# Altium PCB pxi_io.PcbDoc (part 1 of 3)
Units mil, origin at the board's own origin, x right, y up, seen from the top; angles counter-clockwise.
Board outline 6300 x 3935 mil, 2 copper layers (Top Layer, Bottom Layer); 257 components, 420 nets, 1532 pads, 239 vias.
Unrouted connection lines stored in the file: 158.
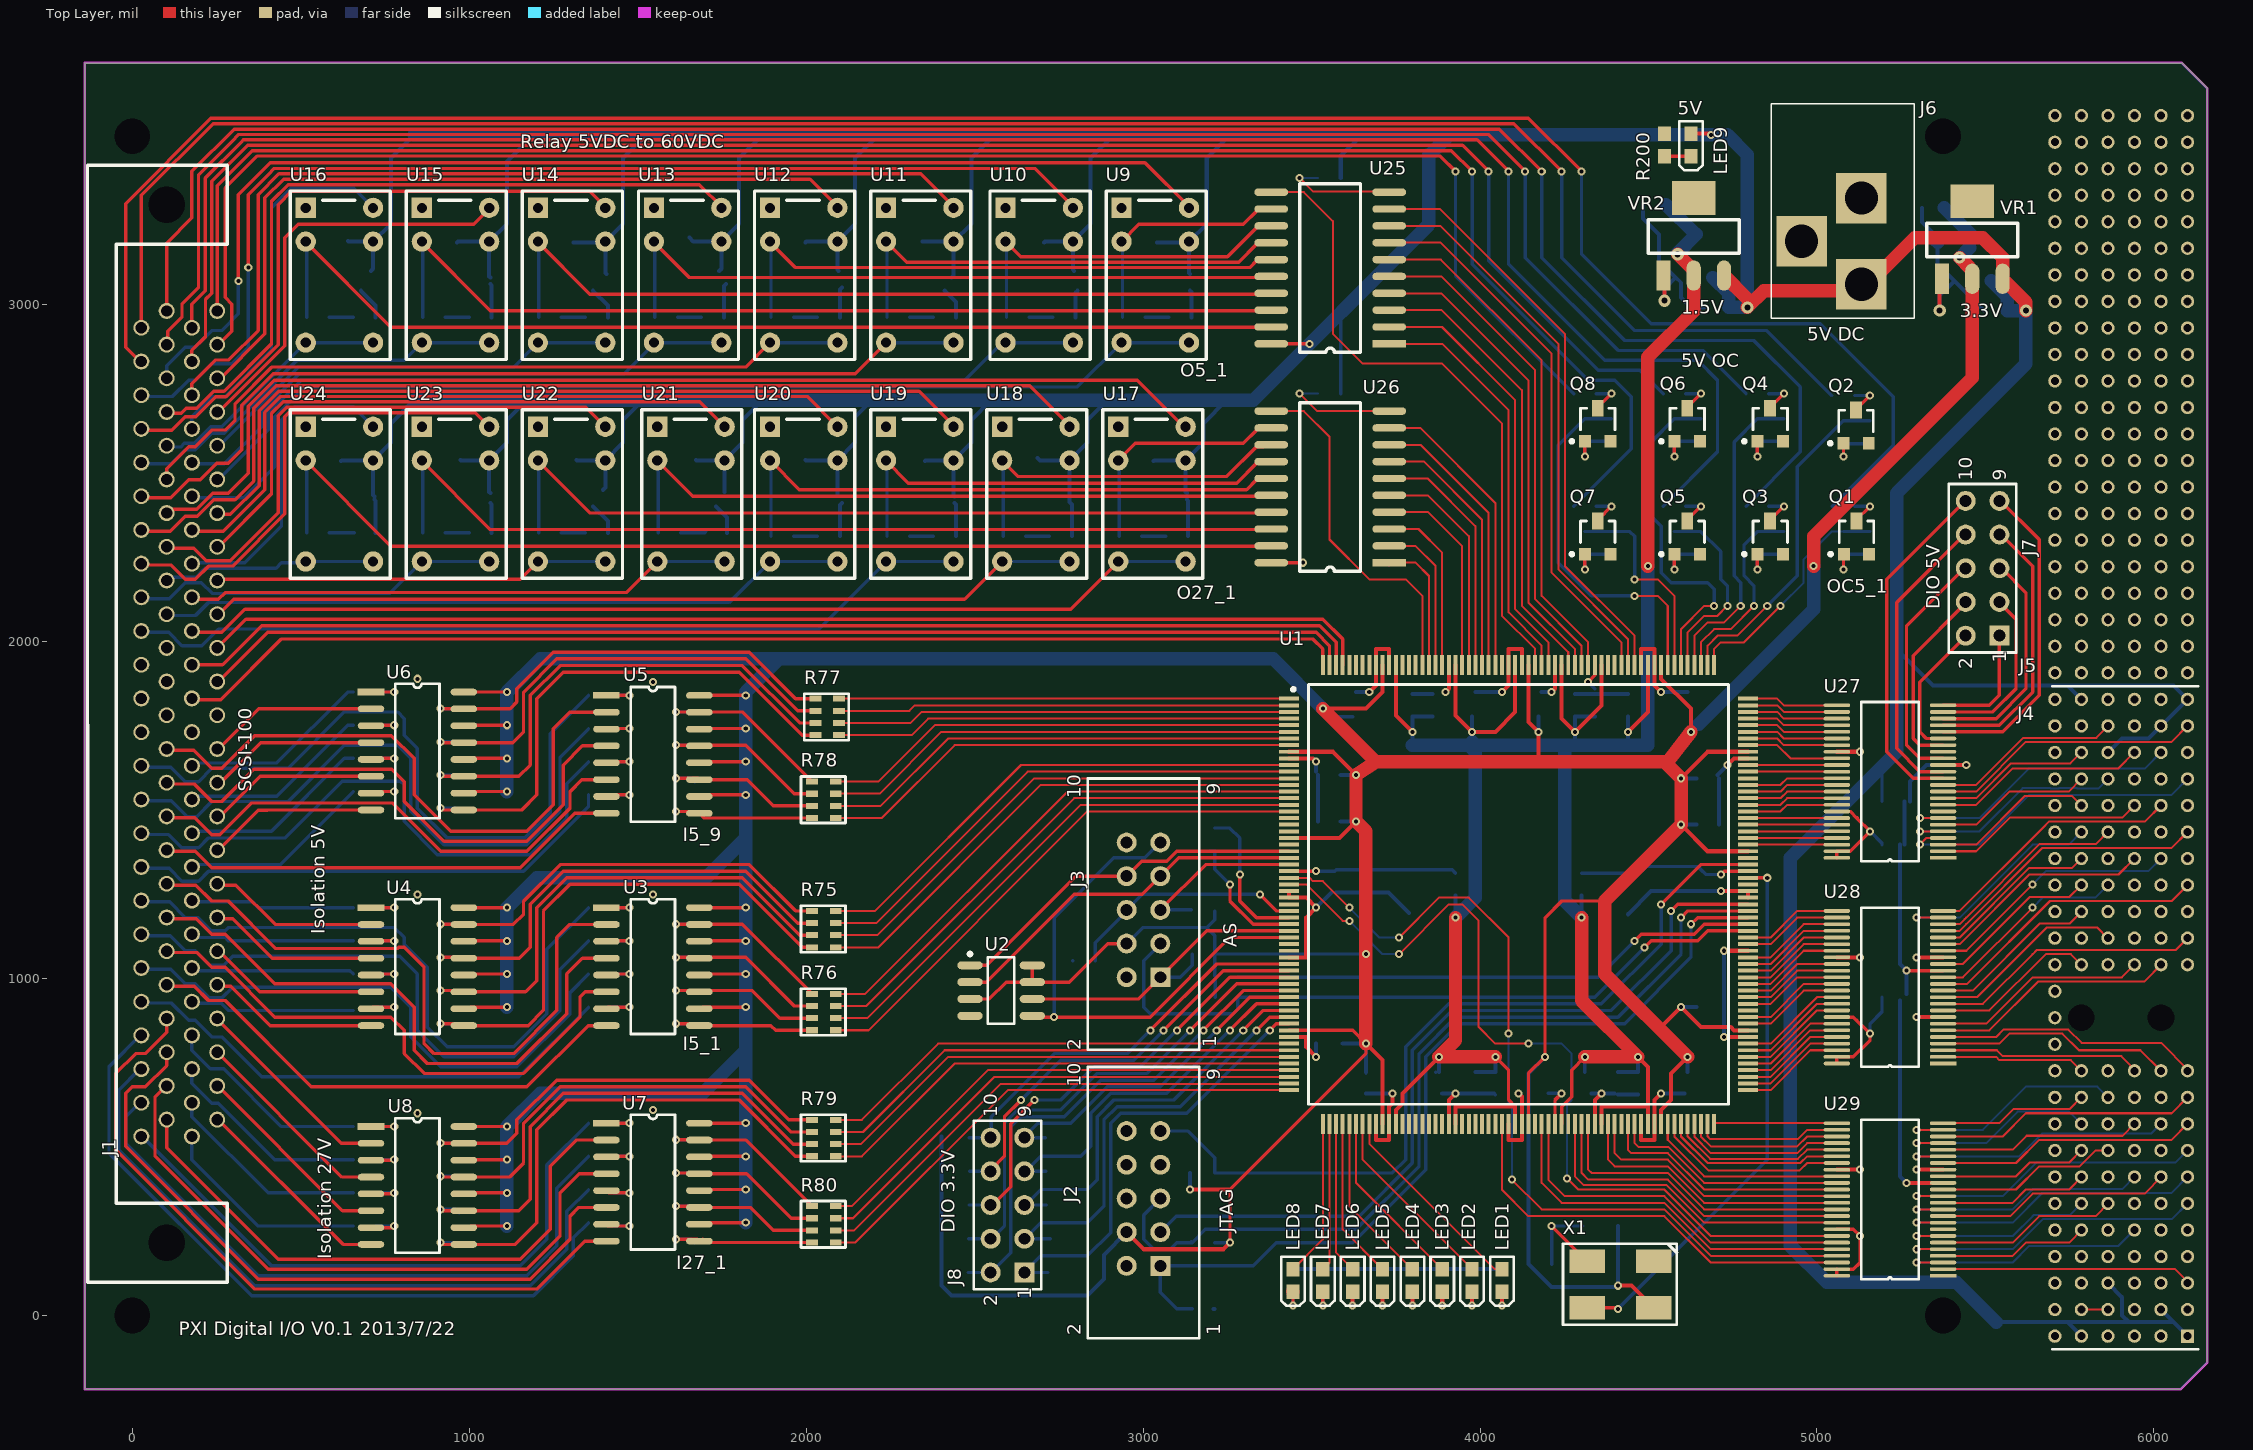
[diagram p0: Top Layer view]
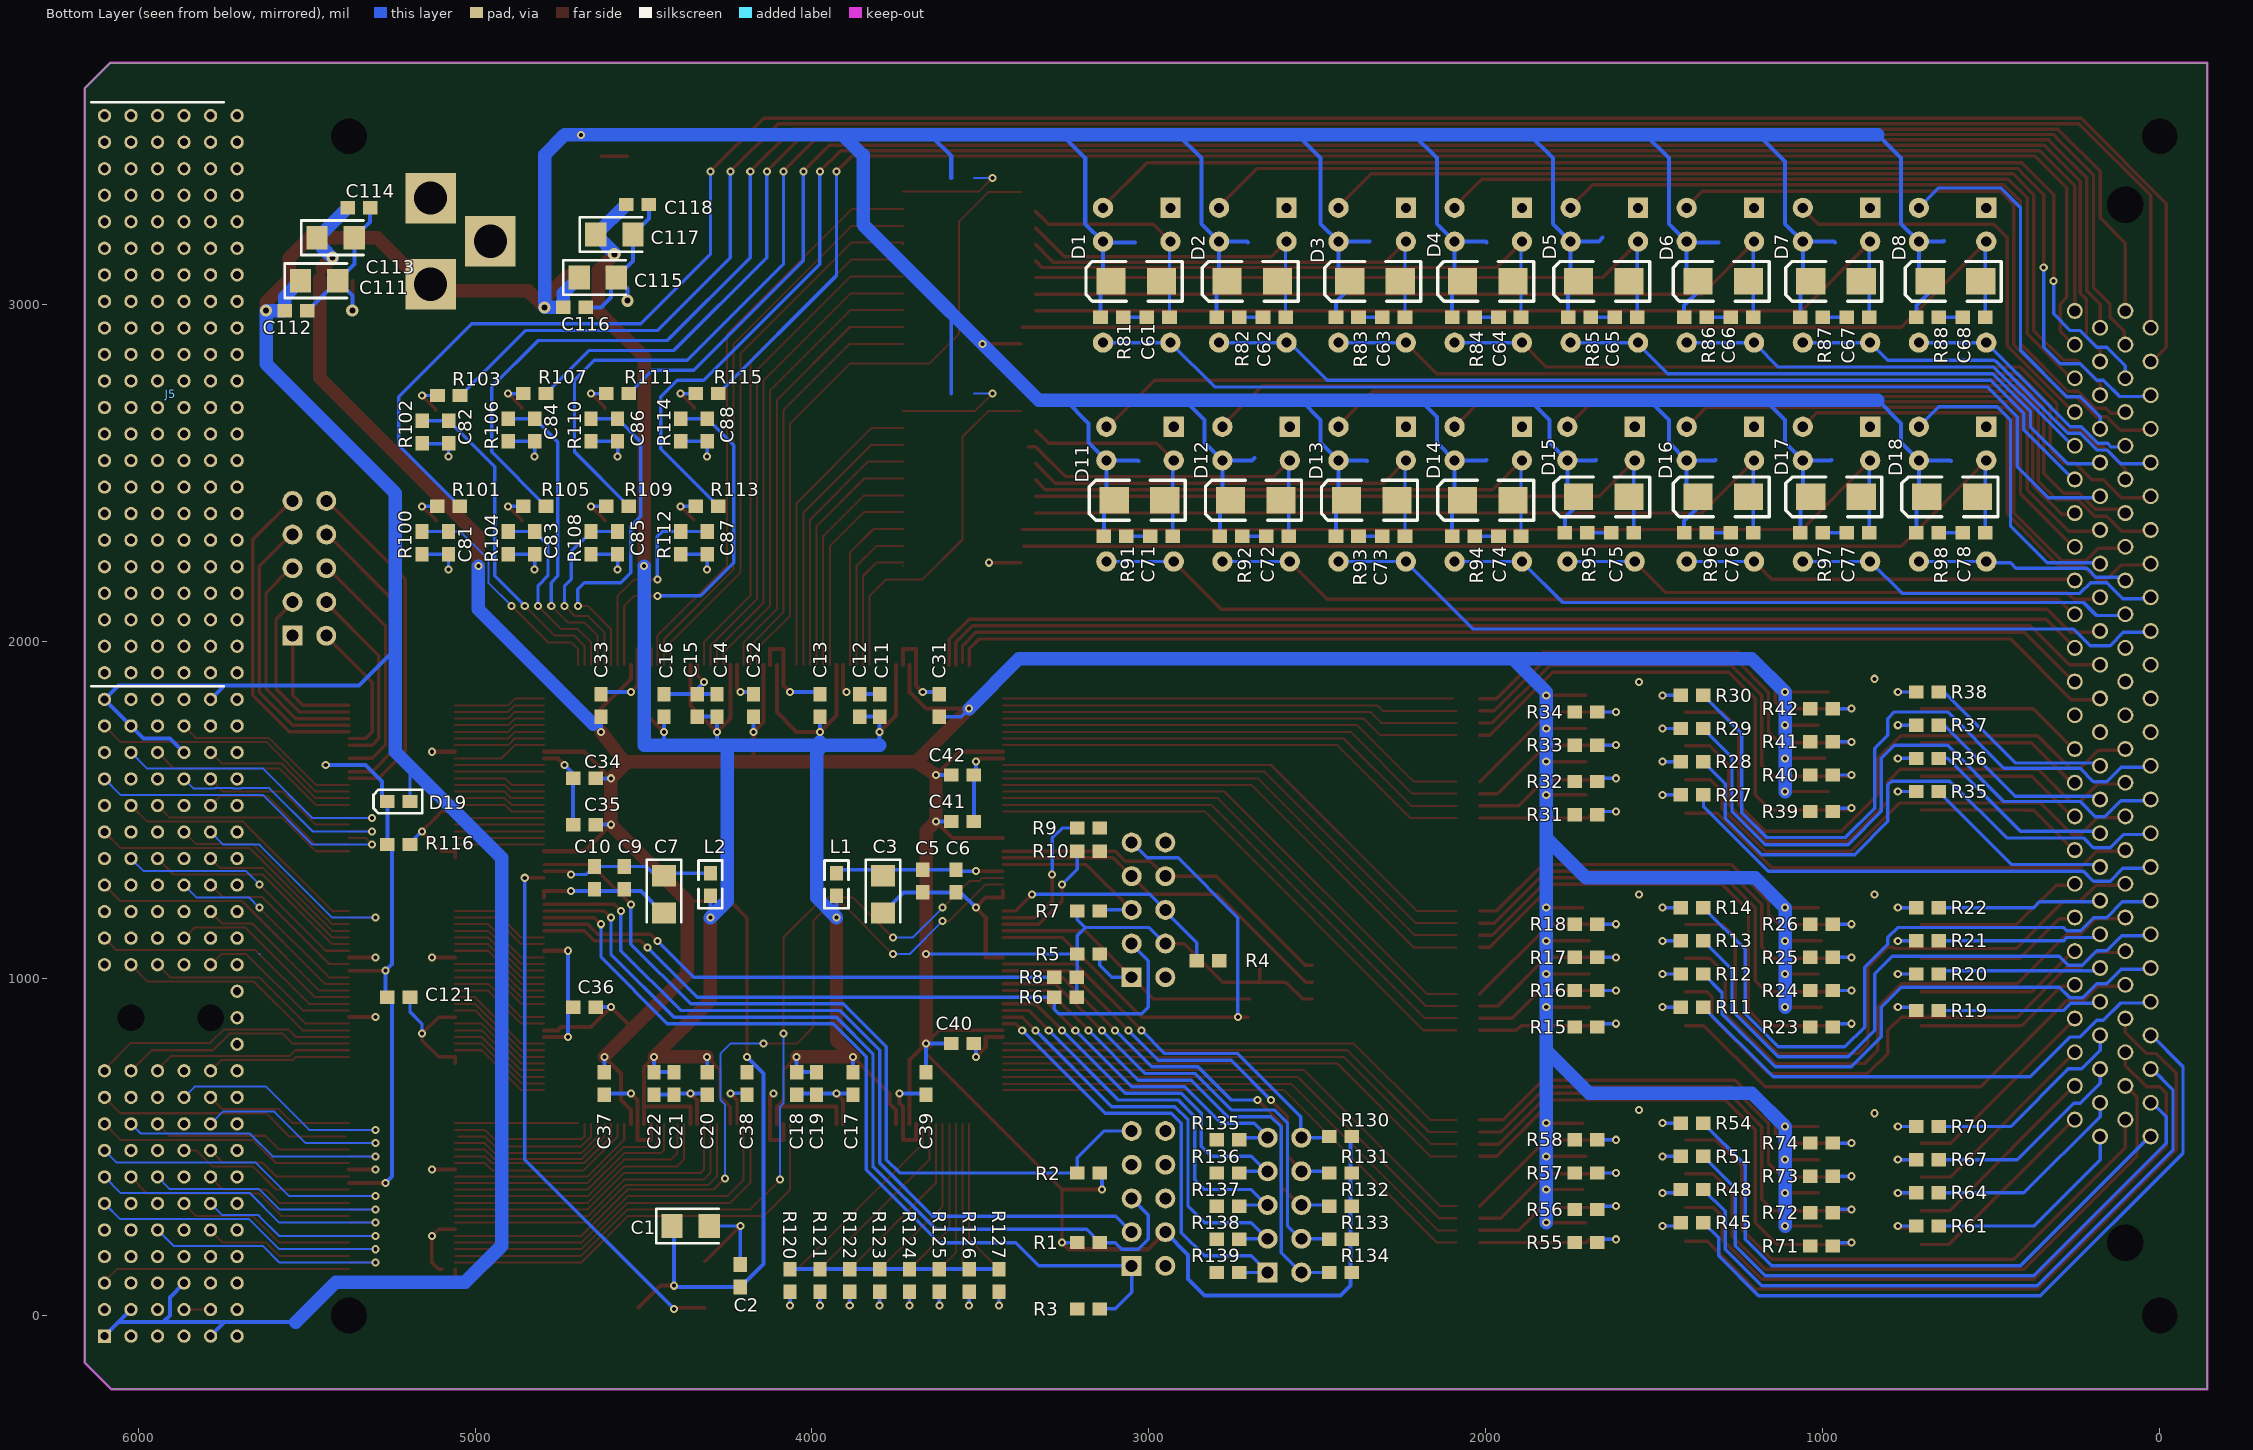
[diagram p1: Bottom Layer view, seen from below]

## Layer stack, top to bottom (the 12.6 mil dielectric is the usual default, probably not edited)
Top Layer: signal copper 1.4
Dielectric: core 12.6, FR-4, Dk 4.8
Bottom Layer: signal copper 1.4

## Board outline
-141.34,3717.05 6083.66,3717.05 6158.66,3642.05 6158.66,3637.05 6158.66,-137.95 6078.66,-217.95 -141.34,-217.95

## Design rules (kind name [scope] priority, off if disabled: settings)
Clearance [All] p1: gap=6
ComponentClearance [All] p1: gap=0 collisioncheckmode=3 verticalgap=10 showdistances=FALSE
FabricationTestPointUsage TestPointUsage [All] p1: valid=0 allowmultiple=FALSE
FabricationTestpoint Testpoint [All] p1: side=3 testpointundercomponent=TRUE minsize=40 maxsize=100 preferedsize=60 minholesize=0 maxholesize=40 preferedholesize=32 testpointgrid=1 allowsidetop=TRUE allowsidebottom=TRUE usegrid=TRUE gridtolerance=0.01
PolygonConnect [All] p1: connectstyle=Relief reliefconductorwidth=10 reliefentries=4 polygonreliefangle="90 Angle"
RoutingVias [All] p1: holewidth=28 width=50 viastyle="Through Hole" minholewidth=12 minwidth=24 maxholewidth=28 maxwidth=50
SilkscreenOverComponentPads [All] p1: minsilkscreentomaskgap=10
SolderMaskExpansion [All] p1: expansion=4
Width [All] p1: maxlimit=40 minlimit=6 preferedwidth=6
24 further rules are at their usual default settings.

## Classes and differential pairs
component class pxi_io: J1
component class pxi: C111 C112 C113 C114 C115 C116 C117 C118 C121 D19 J4 J5 J6 J7 LED9 R116 R200 U27 U28 U29 VR1 VR2
component class fpga: C1 C2 C3 C5 C6 C7 C9 C10 C11 C12 C13 C14 C15 C16 C17 C18 C19 C20 C21 C22 C31 C32 C33 C34 C35 C36 C37 C38 C39 C40 C41 C42 J2 J3 J8 L1 L2 LED1 LED2 LED3 LED4 LED5 LED6 LED7 LED8 R1 R2 R3 R4 R5 R6 R7 R8 R9 R10 R120 R121 R122 R123 R124 R125 R126 R127 R130 R131 R132 R133 R134 R135 R136 R137 R138 R139 U1 U2 X1
component class digit_out: C61 C62 C63 C64 C65 C66 C67 C68 C71 C72 C73 C74 C75 C76 C77 C78 C81 C82 C83 C84 C85 C86 C87 C88 D1 D2 D3 D4 D5 D6 D7 D8 D11 D12 D13 D14 D15 D16 D17 D18 Q1 Q2 Q3 Q4 Q5 Q6 Q7 Q8 R81 R82 R83 R84 R85 R86 R87 R88 R91 R92 R93 R94 R95 R96 R97 R98 R100 R101 R102 R103 R104 R105 R106 R107 R108 R109 R110 R111 R112 R113 R114 R115 U9 U10 U11 U12 U13 U14 U15 U16 U17 U18 U19 U20 U21 U22 U23 U24 U25 U26
component class digit_in: R11 R12 R13 R14 R15 R16 R17 R18 R19 R20 R21 R22 R23 R24 R25 R26 R27 R28 R29 R30 R31 R32 R33 R34 R35 R36 R37 R38 R39 R40 R41 R42 R45 R48 R51 R54 R55 R56 R57 R58 R61 R64 R67 R70 R71 R72 R73 R74 R75 R76 R77 R78 R79 R80 U3 U4 U5 U6 U7 U8

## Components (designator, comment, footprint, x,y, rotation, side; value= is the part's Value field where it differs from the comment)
C1 "Cap Pol3" CC3216-1206 4360.24,265.75 r180 bottom
C2 "Cap Semi" 1608[0603] 4212.6,118.11 r270 bottom
C3 "Cap Pol3" CC3216-1206 3789.37,1250 r270 bottom
C5 "Cap Semi" 1608[0603] 3671.26,1289.37 r90 bottom
C6 "Cap Semi" 1608[0603] 3572.83,1289.37 r90 bottom
C7 "Cap Pol3" CC3216-1206 4438.98,1250 r270 bottom
C9 "Cap Semi" 1608[0603] 4557.09,1299.21 r90 bottom
C10 "Cap Semi" 1608[0603] 4645.67,1299.21 r90 bottom
C11 "Cap Semi" 1608[0603] 3799.21,1811.02 r270 bottom
C12 "Cap Semi" 1608[0603] 3858.27,1811.02 r270 bottom
C13 "Cap Semi" 1608[0603] 3976.38,1811.02 r270 bottom
C14 "Cap Semi" 1608[0603] 4281.5,1811.02 r270 bottom
C15 "Cap Semi" 1608[0603] 4340.55,1811.02 r270 bottom
C16 "Cap Semi" 1608[0603] 4438.98,1811.02 r270 bottom
C17 "Cap Semi" 1608[0603] 3877.95,688.98 r90 bottom
C18 "Cap Semi" 1608[0603] 4045.28,688.98 r90 bottom
C19 "Cap Semi" 1608[0603] 3986.22,688.98 r90 bottom
C20 "Cap Semi" 1608[0603] 4311.02,688.98 r90 bottom
C21 "Cap Semi" 1608[0603] 4409.45,688.98 r90 bottom
C22 "Cap Semi" 1608[0603] 4468.5,688.98 r90 bottom
C31 "Cap Semi" 1608[0603] 3622.05,1811.02 r270 bottom
C32 "Cap Semi" 1608[0603] 4173.23,1811.02 r270 bottom
C33 "Cap Semi" 1608[0603] 4625.98,1811.02 r270 bottom
C34 "Cap Semi" 1608[0603] 4675.2,1594.49 r180 bottom
C35 "Cap Semi" 1608[0603] 4675.2,1456.69 r180 bottom
C36 "Cap Semi" 1608[0603] 4675.2,915.35 r180 bottom
C37 "Cap Semi" 1608[0603] 4616.14,688.98 r90 bottom
C38 "Cap Semi" 1608[0603] 4192.91,688.98 r90 bottom
C39 "Cap Semi" 1608[0603] 3661.42,688.98 r90 bottom
C40 "Cap Semi" 1608[0603] 3553.15,807.09 r0 bottom
C41 "Cap Semi" 1608[0603] 3553.15,1466.54 r0 bottom
C42 "Cap Semi" 1608[0603] 3553.15,1604.33 r0 bottom
C61 "Cap Semi" 1608[0603] 2972.44,2962.6 r180 bottom
C62 "Cap Semi" 1608[0603] 2627.95,2962.6 r180 bottom
C63 "Cap Semi" 1608[0603] 2273.62,2962.6 r180 bottom
C64 "Cap Semi" 1608[0603] 1929.13,2962.6 r180 bottom
C65 "Cap Semi" 1608[0603] 1584.65,2962.6 r180 bottom
C66 "Cap Semi" 1608[0603] 1240.16,2962.6 r180 bottom
C67 "Cap Semi" 1608[0603] 895.67,2962.6 r180 bottom
C68 "Cap Semi" 1608[0603] 551.18,2962.6 r180 bottom
C71 "Cap Semi" 1608[0603] 2962.6,2312.99 r180 bottom
C72 "Cap Semi" 1608[0603] 2618.11,2312.99 r180 bottom
C73 "Cap Semi" 1608[0603] 2273.62,2312.99 r180 bottom
C74 "Cap Semi" 1608[0603] 1929.13,2312.99 r180 bottom
C75 "Cap Semi" 1608[0603] 1594.49,2322.83 r180 bottom
C76 "Cap Semi" 1608[0603] 1240.16,2322.83 r180 bottom
C77 "Cap Semi" 1608[0603] 895.67,2322.83 r180 bottom
C78 "Cap Semi" 1608[0603] 551.18,2322.83 r180 bottom
C81 "Cap Semi" 1608[0603] 5078.74,2293.31 r90 bottom
C82 "Cap Semi" 1608[0603] 5077.88,2622.1 r90 bottom
C83 "Cap Semi" 1608[0603] 4822.83,2293.31 r90 bottom
C84 "Cap Semi" 1608[0603] 4822.83,2627.95 r90 bottom
C85 "Cap Semi" 1608[0603] 4576.77,2293.31 r90 bottom
C86 "Cap Semi" 1608[0603] 4576.77,2627.95 r90 bottom
C87 "Cap Semi" 1608[0603] 4311.02,2293.31 r90 bottom
C88 "Cap Semi" 1608[0603] 4311.02,2627.95 r90 bottom
C111 "Cap Pol3" CC3216-1206 5462.6,3070.87 r180 bottom
C112 "Cap Semi" 1608[0603] 5531.5,2982.28 r0 bottom
C113 "Cap Pol3" CC3216-1206 5413.39,3198.82 r180 bottom
C114 "Cap Semi" 1608[0603] 5344.49,3287.4 r0 bottom
C115 "Cap Pol3" CC3216-1206 4635.83,3080.71 r180 bottom
C116 "Cap Semi" 1608[0603] 4704.72,2992.13 r0 bottom
C117 "Cap Pol3" CC3216-1206 4586.61,3208.66 r180 bottom
C118 "Cap Semi" 1608[0603] 4517.72,3297.24 r0 bottom
C121 "Cap Semi" 1608[0603] 5226.38,944.88 r0 bottom
D1 "Diode" IN5817 2962.6,3169.29 r0 bottom
D2 "Diode" IN5817 2618.11,3169.29 r0 bottom
D3 "Diode" IN5817 2253.94,3169.29 r0 bottom
D4 "Diode" IN5817 1919.29,3169.29 r0 bottom
D5 "Diode" IN5817 1574.8,3169.29 r0 bottom
D6 "Diode" IN5817 1220.47,3169.29 r0 bottom
D7 "Diode" IN5817 885.83,3169.29 r0 bottom
D8 "Diode" IN5817 531.5,3169.29 r0 bottom
D11 "Diode" IN5817 2952.76,2519.69 r0 bottom
D12 "Diode" IN5817 2608.27,2519.69 r0 bottom
D13 "Diode" IN5817 2263.78,2519.69 r0 bottom
D14 "Diode" IN5817 1919.29,2519.69 r0 bottom
D15 "Diode" IN5817 1574.8,2529.53 r0 bottom
D16 "Diode" IN5817 1220.47,2529.53 r0 bottom
D17 "Diode" IN5817 885.83,2529.53 r0 bottom
D18 "Diode" IN5817 541.34,2529.53 r0 bottom
D19 "Diode" D1608-0603 5226.38,1525.59 r0 bottom
J1 "Connector 100" SCSI-100 177.17,531.5 r90 top locked
J2 "Header 5X2" HDR2X5_JTAG 3051.18,147.64 r90 top locked
J3 "Header 5X2" HDR2X5_JTAG 3051.18,1003.94 r90 top locked
J4 "352068-1" BTB2-H135F 6099.61,-61.02 r90 top locked
J5 "352152-1" BTB2-H132FA 6099.61,1907.48 r270 bottom locked
J6 "PWP_CON" POWER_CON_EXTERN 5088.58,3346.46 r90 top locked
J7 "DIO 5V" HDR2X5 5541.34,2017.72 r90 top locked
J8 "DIO 3.3V" HDR2X5 2647.64,127.95 r90 top locked
L1 "Inductor" C1608-0603 3927.17,1279.53 r90 bottom
L2 "Inductor" C1608-0603 4301.18,1279.53 r90 bottom
LED1 "LED2" D1608-0603 4064.96,104.33 r270 top
LED2 "LED2" D1608-0603 3976.38,104.33 r270 top
LED3 "LED2" D1608-0603 3887.8,104.33 r270 top
LED4 "LED2" D1608-0603 3799.21,104.33 r270 top
LED5 "LED2" D1608-0603 3710.63,104.33 r270 top
LED6 "LED2" D1608-0603 3622.05,104.33 r270 top
LED7 "LED2" D1608-0603 3533.46,104.33 r270 top
LED8 "LED2" D1608-0603 3444.88,104.33 r270 top
LED9 "LED2" D1608-0603 4625.98,3474.41 r270 top
Q1 "QNPN" SO3 5000,2500 r0 top
Q2 "QNPN" SO3 4999.14,2828.8 r0 top
Q3 "QNPN" SO3 4744.09,2500 r0 top
Q4 "QNPN" SO3 4744.09,2834.65 r0 top
Q5 "QNPN" SO3 4498.03,2500 r0 top
Q6 "QNPN" SO3 4498.03,2834.65 r0 top
Q7 "QNPN" SO3 4232.28,2500 r0 top
Q8 "QNPN" SO3 4232.28,2834.65 r0 top
R1 "Res Semi" 1608[0603] 3179.13,216.54 r0 bottom
R2 "Res Semi" 1608[0603] 3179.13,423.23 r180 bottom
R3 "Res Semi" 1608[0603] 3179.13,19.68 r0 bottom
R4 "Res Semi" 1608[0603] 2824.8,1053.15 r0 bottom
R5 "Res Semi" 1608[0603] 3179.13,1072.83 r180 bottom
R6 "Res Semi" 1608[0603] 3248.03,944.88 r0 bottom
R7 "Res Semi" 1608[0603] 3179.13,1200.79 r180 bottom
R8 "Res Semi" 1608[0603] 3248.03,1003.94 r0 bottom
R9 "Res Semi" 1608[0603] 3179.13,1446.85 r180 bottom
R10 "Res Semi" 1608[0603] 3179.13,1377.95 r180 bottom
R11 "Res Semi" 1608[0603] 1387.8,915.35 r0 bottom
R12 "Res Semi" 1608[0603] 1387.8,1013.78 r0 bottom
R13 "Res Semi" 1608[0603] 1387.8,1112.2 r0 bottom
R14 "Res Semi" 1608[0603] 1387.8,1210.63 r0 bottom
R15 "Res Semi" 1608[0603] 1702.76,856.3 r0 bottom
R16 "Res Semi" 1608[0603] 1702.76,964.57 r0 bottom
R17 "Res Semi" 1608[0603] 1702.76,1062.99 r0 bottom
R18 "Res Semi" 1608[0603] 1702.76,1161.42 r0 bottom
R19 "Res Semi" 1608[0603] 688.98,905.51 r0 bottom
R20 "Res Semi" 1608[0603] 688.98,1013.78 r0 bottom
R21 "Res Semi" 1608[0603] 688.98,1112.2 r0 bottom
R22 "Res Semi" 1608[0603] 688.98,1210.63 r0 bottom
R23 "Res Semi" 1608[0603] 1003.94,856.3 r0 bottom
R24 "Res Semi" 1608[0603] 1003.94,964.57 r0 bottom
R25 "Res Semi" 1608[0603] 1003.94,1062.99 r0 bottom
R26 "Res Semi" 1608[0603] 1003.94,1161.42 r0 bottom
R27 "Res Semi" 1608[0603] 1387.8,1545.28 r0 bottom
R28 "Res Semi" 1608[0603] 1387.8,1643.7 r0 bottom
R29 "Res Semi" 1608[0603] 1387.8,1742.13 r0 bottom
R30 "Res Semi" 1608[0603] 1387.8,1840.55 r0 bottom
R31 "Res Semi" 1608[0603] 1702.76,1486.22 r0 bottom
R32 "Res Semi" 1608[0603] 1702.76,1584.65 r0 bottom
R33 "Res Semi" 1608[0603] 1702.76,1692.91 r0 bottom
R34 "Res Semi" 1608[0603] 1702.76,1791.34 r0 bottom
R35 "Res Semi" 1608[0603] 688.98,1555.12 r0 bottom
R36 "Res Semi" 1608[0603] 688.98,1653.54 r0 bottom
R37 "Res Semi" 1608[0603] 688.98,1751.97 r0 bottom
R38 "Res Semi" 1608[0603] 688.98,1850.39 r0 bottom
R39 "Res Semi" 1608[0603] 1003.94,1496.06 r0 bottom
R40 "Res Semi" 1608[0603] 1003.94,1604.33 r0 bottom
R41 "Res Semi" 1608[0603] 1003.94,1702.76 r0 bottom
R42 "Res Semi" 1608[0603] 1003.94,1801.18 r0 bottom
R45 "Res Semi" 1608[0603] 1387.8,275.59 r0 bottom
R48 "Res Semi" 1608[0603] 1387.8,374.02 r0 bottom
R51 "Res Semi" 1608[0603] 1387.8,472.44 r0 bottom
R54 "Res Semi" 1608[0603] 1387.8,570.87 r0 bottom
R55 "Res Semi" 1608[0603] 1702.76,216.54 r0 bottom
R56 "Res Semi" 1608[0603] 1702.76,314.96 r0 bottom
R57 "Res Semi" 1608[0603] 1702.76,423.23 r0 bottom
R58 "Res Semi" 1608[0603] 1702.76,521.65 r0 bottom
R61 "Res Semi" 1608[0603] 688.98,265.75 r0 bottom
R64 "Res Semi" 1608[0603] 688.98,364.17 r0 bottom
R67 "Res Semi" 1608[0603] 688.98,462.6 r0 bottom
R70 "Res Semi" 1608[0603] 688.98,561.02 r0 bottom
R71 "Res Semi" 1608[0603] 1003.94,206.69 r0 bottom
R72 "Res Semi" 1608[0603] 1003.94,305.12 r0 bottom
R73 "Res Semi" 1608[0603] 1003.94,413.39 r0 bottom
R74 "Res Semi" 1608[0603] 1003.94,511.81 r0 bottom
R75 "R0603_4" R0603_4 2017.72,1200.79 r0 top
R76 "R0603_4" R0603_4 2017.72,954.72 r0 top
R77 "R0603_4" R0603_4 2027.56,1830.71 r0 top
R78 "R0603_4" R0603_4 2017.72,1584.65 r0 top
R79 "R0603_4" R0603_4 2017.72,580.71 r0 top
R80 "R0603_4" R0603_4 2017.72,324.8 r0 top
R81 "Res Semi" 1608[0603] 3110.24,2962.6 r0 bottom
R82 "Res Semi" 1608[0603] 2765.75,2962.6 r0 bottom
R83 "Res Semi" 1608[0603] 2411.42,2962.6 r0 bottom
R84 "Res Semi" 1608[0603] 2066.93,2962.6 r0 bottom
R85 "Res Semi" 1608[0603] 1722.44,2962.6 r0 bottom
R86 "Res Semi" 1608[0603] 1377.95,2962.6 r0 bottom
R87 "Res Semi" 1608[0603] 1033.46,2962.6 r0 bottom
R88 "Res Semi" 1608[0603] 688.98,2962.6 r0 bottom
R91 "Res Semi" 1608[0603] 3100.39,2312.99 r0 bottom
R92 "Res Semi" 1608[0603] 2755.91,2312.99 r0 bottom
R93 "Res Semi" 1608[0603] 2411.42,2312.99 r0 bottom
R94 "Res Semi" 1608[0603] 2066.93,2312.99 r0 bottom
R95 "Res Semi" 1608[0603] 1732.28,2322.83 r0 bottom
R96 "Res Semi" 1608[0603] 1377.95,2322.83 r0 bottom
R97 "Res Semi" 1608[0603] 1033.46,2322.83 r0 bottom
R98 "Res Semi" 1608[0603] 688.98,2322.83 r0 bottom
R100 "Res Semi" 1608[0603] 5157.48,2293.31 r270 bottom
R101 "Res Semi" 1608[0603] 5078.74,2401.57 r180 bottom
R102 "Res Semi" 1608[0603] 5156.62,2622.1 r270 bottom
R103 "Res Semi" 1608[0603] 5077.88,2730.37 r180 bottom
R104 "Res Semi" 1608[0603] 4901.57,2293.31 r270 bottom
R105 "Res Semi" 1608[0603] 4822.83,2401.57 r180 bottom
R106 "Res Semi" 1608[0603] 4901.57,2627.95 r270 bottom
R107 "Res Semi" 1608[0603] 4822.83,2736.22 r180 bottom
R108 "Res Semi" 1608[0603] 4655.51,2293.31 r270 bottom
R109 "Res Semi" 1608[0603] 4576.77,2401.57 r180 bottom
R110 "Res Semi" 1608[0603] 4655.51,2627.95 r270 bottom
R111 "Res Semi" 1608[0603] 4576.77,2736.22 r180 bottom
R112 "Res Semi" 1608[0603] 4389.76,2293.31 r270 bottom
R113 "Res Semi" 1608[0603] 4311.02,2401.57 r180 bottom
R114 "Res Semi" 1608[0603] 4389.76,2627.95 r270 bottom
R115 "Res Semi" 1608[0603] 4311.02,2736.22 r180 bottom
R116 "Res Semi" 1608[0603] 5226.38,1397.64 r0 bottom
R120 "Res Semi" 1608[0603] 4064.96,104.33 r90 bottom
R121 "Res Semi" 1608[0603] 3976.38,104.33 r90 bottom
R122 "Res Semi" 1608[0603] 3887.8,104.33 r90 bottom
R123 "Res Semi" 1608[0603] 3799.21,104.33 r90 bottom
R124 "Res Semi" 1608[0603] 3710.63,104.33 r90 bottom
R125 "Res Semi" 1608[0603] 3622.05,104.33 r90 bottom
R126 "Res Semi" 1608[0603] 3533.46,104.33 r90 bottom
R127 "Res Semi" 1608[0603] 3444.88,104.33 r90 bottom
R130 "Res Semi" 1608[0603] 2431.1,531.5 r180 bottom
R131 "Res Semi" 1608[0603] 2431.1,423.23 r180 bottom
R132 "Res Semi" 1608[0603] 2431.1,324.8 r180 bottom
R133 "Res Semi" 1608[0603] 2431.1,226.38 r180 bottom
R134 "Res Semi" 1608[0603] 2431.1,127.95 r180 bottom
R135 "Res Semi" 1608[0603] 2765.75,521.65 r180 bottom
R136 "Res Semi" 1608[0603] 2765.75,423.23 r180 bottom
R137 "Res Semi" 1608[0603] 2765.75,324.8 r180 bottom
R138 "Res Semi" 1608[0603] 2765.75,226.38 r180 bottom
R139 "Res Semi" 1608[0603] 2765.75,127.95 r180 bottom
R200 "Res Semi" 1608[0603] 4547.24,3474.41 r270 top (schematic designator R140)
U1 "EP1C12Q240C6" PQFP240 4114.17,1250 r0 top locked
U2 "EPCS1SI8" SOIC8_L 2578.74,964.57 r0 top
U3 "TLP281-4" TLP281-4 1407.48,1210.63 r0 top
U4 "TLP281-4" TLP281-4 708.66,1210.63 r0 top
U5 "TLP281-4" TLP281-4 1407.48,1840.55 r0 top
U6 "TLP281-4" TLP281-4 708.66,1850.39 r0 top
U7 "TLP281-4" TLP281-4 1407.48,570.87 r0 top
U8 "TLP281-4" TLP281-4 708.66,561.02 r0 top locked
U9 "G5V-1" G5V-1-DIP 2736.22,3287.4 r0 top
U10 "G5V-1" G5V-1-DIP 2391.73,3287.4 r0 top
U11 "G5V-1" G5V-1-DIP 2037.4,3287.4 r0 top
U12 "G5V-1" G5V-1-DIP 1692.91,3287.4 r0 top
U13 "G5V-1" G5V-1-DIP 1348.43,3287.4 r0 top
U14 "G5V-1" G5V-1-DIP 1003.94,3287.4 r0 top
U15 "G5V-1" G5V-1-DIP 659.45,3287.4 r0 top
U16 "G5V-1" G5V-1-DIP 314.96,3287.4 r0 top
U17 "G5V-1" G5V-1-DIP 2726.38,2637.8 r0 top
U18 "G5V-1" G5V-1-DIP 2381.89,2637.8 r0 top
U19 "G5V-1" G5V-1-DIP 2037.4,2637.8 r0 top
U20 "G5V-1" G5V-1-DIP 1692.91,2637.8 r0 top
U21 "G5V-1" G5V-1-DIP 1358.27,2637.8 r0 top
U22 "G5V-1" G5V-1-DIP 1003.94,2637.8 r0 top
U23 "G5V-1" G5V-1-DIP 659.45,2637.8 r0 top
U24 "G5V-1" G5V-1-DIP 314.96,2637.8 r0 top
U25 "74HC573" SOP20 3730.31,2883.86 r180 top
U26 "74HC573" SOP20 3730.31,2234.25 r180 top
U27 "SN74CBT16210" SSOP48 5374.02,1358.27 r180 top locked
U28 "SN74CBT16210" SSOP48 5374.02,748.03 r180 top locked
U29 "SN74CBT16210" SSOP48 5374.02,118.11 r180 top locked
VR1 "AS1117-3.3V" LM1117 5511.81,3326.77 r90 top locked
VR2 "AS1117-1.5V" LM1117 4685.04,3336.61 r90 top locked
X1 "OSCIL 50MHZ" "OSC -BIG" 4625.98,-68.9 r0 top

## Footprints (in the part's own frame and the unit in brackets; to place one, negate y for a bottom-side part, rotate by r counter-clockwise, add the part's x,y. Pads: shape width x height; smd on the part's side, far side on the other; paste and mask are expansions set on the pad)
1608[0603] [mm] "Chip Capacitor; Body 1.6 x 0.8 mm (LxW typ)"
  rect 1.1x1 smd: 1(-0.85,0) 2(0.85,0)
BTB2-H132FA [mm] "Board-to-Board Connector, Right Angle, Pitch 2mm, 132-Position, Female"
  round 1 hole 0.61: A1(0,0) A2(-2,0) A3(-4,0) A4(-6,0) A5(-8,0) A6(-10,0) A7(-12,0) A8(-14,0) A9(-16,0) A10(-18,0) A11(-20,0) A12(-22,0) A13(-24,0) A14(-26,0) A15(-28,0) A16(-30,0) A17(-32,0) A18(-34,0) A19(-36,0) A20(-38,0) A21(-40,0) A22(-42,0) B1(0,2) B2(-2,2) B3(-4,2) B4(-6,2) B5(-8,2) B6(-10,2) B7(-12,2) B8(-14,2) B9(-16,2) B10(-18,2) B11(-20,2) B12(-22,2) B13(-24,2) B14(-26,2) B15(-28,2) B16(-30,2) B17(-32,2) B18(-34,2) B19(-36,2) B20(-38,2) B21(-40,2) B22(-42,2) C1(0,4) C2(-2,4) C3(-4,4) C4(-6,4) C5(-8,4) C6(-10,4) C7(-12,4) C8(-14,4) C9(-16,4) C10(-18,4) C11(-20,4) C12(-22,4) C13(-24,4) C14(-26,4) C15(-28,4) C16(-30,4) C17(-32,4) C18(-34,4) C19(-36,4) C20(-38,4) C21(-40,4) C22(-42,4) D1(0,6) D2(-2,6) D3(-4,6) D4(-6,6) D5(-8,6) D6(-10,6) D7(-12,6) D8(-14,6) D9(-16,6) D10(-18,6) D11(-20,6) D12(-22,6) D13(-24,6) D14(-26,6) D15(-28,6) D16(-30,6) D17(-32,6) D18(-34,6) D19(-36,6) D20(-38,6) D21(-40,6) D22(-42,6) E1(0,8) E2(-2,8) E3(-4,8) E4(-6,8) E5(-8,8) E6(-10,8) E7(-12,8) E8(-14,8) E9(-16,8) E10(-18,8) E11(-20,8) E12(-22,8) E13(-24,8) E14(-26,8) E15(-28,8) E16(-30,8) E17(-32,8) E18(-34,8) E19(-36,8) E20(-38,8) E21(-40,8) E22(-42,8) F1(0,10) F2(-2,10) F3(-4,10) F4(-6,10) F5(-8,10) F6(-10,10) F7(-12,10) F8(-14,10) F9(-16,10) F10(-18,10) F11(-20,10) F12(-22,10) F13(-24,10) F14(-26,10) F15(-28,10) F16(-30,10) F17(-32,10) F18(-34,10) F19(-36,10) F20(-38,10) F21(-40,10) F22(-42,10)
  silkscreen extent -43,-1 1,9, body extent -43,-10.8 1,10.2, height 7.8
BTB2-H135F [mm] "Board-to-Board Connector, Right Angle, Pitch 2mm, 135-Position, Female"
  rect 1x1 hole 0.61: A1(0,0)
  round 1 hole 0.61: A2(2,0) A3(4,0) A4(6,0) A5(8,0) A6(10,0) A7(12,0) A8(14,0) A9(16,0) A10(18,0) A11(20,0) A15(28,0) A16(30,0) A17(32,0) A18(34,0) A19(36,0) A20(38,0) A21(40,0) A22(42,0) A23(44,0) A24(46,0) A25(48,0) B1(0,2) B2(2,2) B3(4,2) B4(6,2) B5(8,2) B6(10,2) B7(12,2) B8(14,2) B9(16,2) B10(18,2) B11(20,2) B15(28,2) B16(30,2) B17(32,2) B18(34,2) B19(36,2) B20(38,2) B21(40,2) B22(42,2) B23(44,2) B24(46,2) B25(48,2) C1(0,4) C2(2,4) C3(4,4) C4(6,4) C5(8,4) C6(10,4) C7(12,4) C8(14,4) C9(16,4) C10(18,4) C11(20,4) C15(28,4) C16(30,4) C17(32,4) C18(34,4) C19(36,4) C20(38,4) C21(40,4) C22(42,4) C23(44,4) C24(46,4) C25(48,4) D1(0,6) D2(2,6) D3(4,6) D4(6,6) D5(8,6) D6(10,6) D7(12,6) D8(14,6) D9(16,6) D10(18,6) D11(20,6) D15(28,6) D16(30,6) D17(32,6) D18(34,6) D19(36,6) D20(38,6) D21(40,6) D22(42,6) D23(44,6) D24(46,6) D25(48,6) E1(0,8) E2(2,8) E3(4,8) E4(6,8) E5(8,8) E6(10,8) E7(12,8) E8(14,8) E9(16,8) E10(18,8) E11(20,8) E15(28,8) E16(30,8) E17(32,8) E18(34,8) E19(36,8) E20(38,8) E21(40,8) E22(42,8) E23(44,8) E24(46,8) E25(48,8) F1(0,10) F2(2,10) F3(4,10) F4(6,10) F5(8,10) F6(10,10) F7(12,10) F8(14,10) F9(16,10) F10(18,10) F11(20,10) F12(22,10) F13(24,10) F14(26,10) F15(28,10) F16(30,10) F17(32,10) F18(34,10) F19(36,10) F20(38,10) F21(40,10) F22(42,10) F23(44,10) F24(46,10) F25(48,10)
  silkscreen extent -1,-0.8 49,10.2, body extent -0.95,-13.8 48.95,10.27, height 8.08
C1608-0603 [mm]
  rect 1.1x1 smd: 1(-0.85,0) 2(0.85,0)
  silkscreen extent -1.8,-0.9 1.8,0.9
CC3216-1206 [mm]
  rect 1.6x1.8 smd: 1(-1.4,0) 2(1.4,0)
  silkscreen extent -2.6,-1.3 2.1,1.3
D1608-0603 [mm]
  rect 1.1x1 smd: 1(-0.85,0) 2(0.85,0)
  silkscreen extent -1.78,-0.89 1.91,0.89
G5V-1-DIP [mil]
  rect 60x60 hole 30: 1(200,0)
  round 60 hole 30: 2(200,-100) 5(200,-400) 6(400,-400) 9(400,-100) 10(400,0)
  silkscreen extent 154,-450 451,50
HDR2X5 [mm] "Connector; Header; 5x2 Position"
  rect 1.5x1.5 hole 0.9: 1(0,0)
  round 1.5 hole 0.9: 2(0,2.54) 3(2.54,0) 4(2.54,2.54) 5(5.08,0) 6(5.08,2.54) 7(7.62,0) 8(7.62,2.54) 9(10.16,0) 10(10.16,2.54)
  silkscreen extent -1.27,-1.27 11.43,3.81
HDR2X5_JTAG [mm] "Connector; Header; 5x2 Position"
  rect 1.5x1.5 hole 0.9: 1(0,0)
  round 1.5 hole 0.9: 2(0,2.54) 3(2.54,0) 4(2.54,2.54) 5(5.08,0) 6(5.08,2.54) 7(7.62,0) 8(7.62,2.54) 9(10.16,0) 10(10.16,2.54)
  silkscreen extent -5.46,-2.92 14.99,5.46
IN5817 [mm]
  rect 2.2x2 smd: 1(0,2.54) 2(3.81,2.54)
  silkscreen extent -1.55,1.04 5.69,4.04
LM1117 [mil]
  rect 90x42 smd: 1(-250,141)
  oval 90x42 smd: 2(-250,51) 3(-250,-39)
  rect 100x130 smd: 4(-20,51)
  silkscreen extent -184,-84 -85,186
"OSC -BIG" [mil]
  rect 105x70 smd: 1(-111,230) 2(-307.85,230) 3(-308,92) 4(-111,92.2)
  silkscreen extent -380,42 -42,282
POWER_CON_EXTERN [mm]
  rect 3.8x3.8 hole 2.5: 1(-7.264,-1.092) 2(-0.764,-1.092) 3(-4.014,3.408)
  silkscreen extent -9.8,-5.08 6.35,5.69
PQFP240 [mm] "byTX chaned for cyclone FPGA"
  rect 1.5x0.3 smd: 1(-17.3,14.75) 2(-17.3,14.25) 3(-17.3,13.75) 4(-17.3,13.25) 5(-17.3,12.75) 6(-17.3,12.25) 7(-17.3,11.75) 8(-17.3,11.25) 9(-17.3,10.75) 10(-17.3,10.25) 11(-17.3,9.75) 12(-17.3,9.25) 13(-17.3,8.75) 14(-17.3,8.25) 15(-17.3,7.75) 16(-17.3,7.25) 17(-17.3,6.75) 18(-17.3,6.25) 19(-17.3,5.75) 20(-17.3,5.25) 21(-17.3,4.75) 22(-17.3,4.25) 23(-17.3,3.75) 24(-17.3,3.25) 25(-17.3,2.75) 26(-17.3,2.25) 27(-17.3,1.75) 28(-17.3,1.25) 29(-17.3,0.75) 30(-17.3,0.25) 31(-17.3,-0.25) 32(-17.3,-0.75) 33(-17.3,-1.25) 34(-17.3,-1.75) 35(-17.3,-2.25) 36(-17.3,-2.75) 37(-17.3,-3.25) 38(-17.3,-3.75) 39(-17.3,-4.25) 40(-17.3,-4.75) 41(-17.3,-5.25) 42(-17.3,-5.75) 43(-17.3,-6.25) 44(-17.3,-6.75) 45(-17.3,-7.25) 46(-17.3,-7.75) 47(-17.3,-8.25) 48(-17.3,-8.75) 49(-17.3,-9.25) 50(-17.3,-9.75) 51(-17.3,-10.25) 52(-17.3,-10.75) 53(-17.3,-11.25) 54(-17.3,-11.75) 55(-17.3,-12.25) 56(-17.3,-12.75) 57(-17.3,-13.25) 58(-17.3,-13.75) 59(-17.3,-14.25) 60(-17.3,-14.75) 121(17.3,-14.75) 122(17.3,-14.25) 123(17.3,-13.75) 124(17.3,-13.25) 125(17.3,-12.75) 126(17.3,-12.25) 127(17.3,-11.75) 128(17.3,-11.25) 129(17.3,-10.75) 130(17.3,-10.25) 131(17.3,-9.75) 132(17.3,-9.25) 133(17.3,-8.75) 134(17.3,-8.25) 135(17.3,-7.75) 136(17.3,-7.25) 137(17.3,-6.75) 138(17.3,-6.25) 139(17.3,-5.75) 140(17.3,-5.25) 141(17.3,-4.75) 142(17.3,-4.25) 143(17.3,-3.75) 144(17.3,-3.25) 145(17.3,-2.75) 146(17.3,-2.25) 147(17.3,-1.75) 148(17.3,-1.25) 149(17.3,-0.75) 150(17.3,-0.25) 151(17.3,0.25) 152(17.3,0.75) 153(17.3,1.25) 154(17.3,1.75) 155(17.3,2.25) 156(17.3,2.75) 157(17.3,3.25) 158(17.3,3.75) 159(17.3,4.25) 160(17.3,4.75) 161(17.3,5.25) 162(17.3,5.75) 163(17.3,6.25) 164(17.3,6.75) 165(17.3,7.25) 166(17.3,7.75) 167(17.3,8.25) 168(17.3,8.75) 169(17.3,9.25) 170(17.3,9.75) 171(17.3,10.25) 172(17.3,10.75) 173(17.3,11.25) 174(17.3,11.75) 175(17.3,12.25) 176(17.3,12.75) 177(17.3,13.25) 178(17.3,13.75) 179(17.3,14.25) 180(17.3,14.75)
  rect 0.3x1.5 smd: 61(-14.75,-17.3) 62(-14.25,-17.3) 63(-13.75,-17.3) 64(-13.25,-17.3) 65(-12.75,-17.3) 66(-12.25,-17.3) 67(-11.75,-17.3) 68(-11.25,-17.3) 69(-10.75,-17.3) 70(-10.25,-17.3) 71(-9.75,-17.3) 72(-9.25,-17.3) 73(-8.75,-17.3) 74(-8.25,-17.3) 75(-7.75,-17.3) 76(-7.25,-17.3) 77(-6.75,-17.3) 78(-6.25,-17.3) 79(-5.75,-17.3) 80(-5.25,-17.3) 81(-4.75,-17.3) 82(-4.25,-17.3) 83(-3.75,-17.3) 84(-3.25,-17.3) 85(-2.75,-17.3) 86(-2.25,-17.3) 87(-1.75,-17.3) 88(-1.25,-17.3) 89(-0.75,-17.3) 90(-0.25,-17.3) 91(0.25,-17.3) 92(0.75,-17.3) 93(1.25,-17.3) 94(1.75,-17.3) 95(2.25,-17.3) 96(2.75,-17.3) 97(3.25,-17.3) 98(3.75,-17.3) 99(4.25,-17.3) 100(4.75,-17.3) 101(5.25,-17.3) 102(5.75,-17.3) 103(6.25,-17.3) 104(6.75,-17.3) 105(7.25,-17.3) 106(7.75,-17.3) 107(8.25,-17.3) 108(8.75,-17.3) 109(9.25,-17.3) 110(9.75,-17.3) 111(10.25,-17.3) 112(10.75,-17.3) 113(11.25,-17.3) 114(11.75,-17.3) 115(12.25,-17.3) 116(12.75,-17.3) 117(13.25,-17.3) 118(13.75,-17.3) 119(14.25,-17.3) 120(14.75,-17.3) 181(14.75,17.3) 182(14.25,17.3) 183(13.75,17.3) 184(13.25,17.3) 185(12.75,17.3) 186(12.25,17.3) 187(11.75,17.3) 188(11.25,17.3) 189(10.75,17.3) 190(10.25,17.3) 191(9.75,17.3) 192(9.25,17.3) 193(8.75,17.3) 194(8.25,17.3) 195(7.75,17.3) 196(7.25,17.3) 197(6.75,17.3) 198(6.25,17.3) 199(5.75,17.3) 200(5.25,17.3) 201(4.75,17.3) 202(4.25,17.3) 203(3.75,17.3) 204(3.25,17.3) 205(2.75,17.3) 206(2.25,17.3) 207(1.75,17.3) 208(1.25,17.3) 209(0.75,17.3) 210(0.25,17.3) 211(-0.25,17.3) 212(-0.75,17.3) 213(-1.25,17.3) 214(-1.75,17.3) 215(-2.25,17.3) 216(-2.75,17.3) 217(-3.25,17.3) 218(-3.75,17.3) 219(-4.25,17.3) 220(-4.75,17.3) 221(-5.25,17.3) 222(-5.75,17.3) 223(-6.25,17.3) 224(-6.75,17.3) 225(-7.25,17.3) 226(-7.75,17.3) 227(-8.25,17.3) 228(-8.75,17.3) 229(-9.25,17.3) 230(-9.75,17.3) 231(-10.25,17.3) 232(-10.75,17.3) 233(-11.25,17.3) 234(-11.75,17.3) 235(-12.25,17.3) 236(-12.75,17.3) 237(-13.25,17.3) 238(-13.75,17.3) 239(-14.25,17.3) 240(-14.75,17.3)
  silkscreen extent -17.1,-15.83 15.83,15.83
R0603_4 [mil] "for ResPackX4____OK!"
  rect 35x18 smd: 1(0,0) 2(0,-36) 3(0,-72) 4(0,-108) 5(70.16,-108) 6(70.16,-72) 7(70.16,-36) 8(70.16,0)
  silkscreen extent -33,-123 99,15
SCSI-100 [mm]
  round 1.2 hole 0.85: 1(0,0) 2(1.27,-1.905) 3(2.54,0) 4(3.81,-1.905) 5(5.08,0) 6(6.35,-1.905) 7(7.62,0) 8(8.89,-1.905) 9(10.16,0) 10(11.43,-1.905) 11(12.7,0) 12(13.97,-1.905) 13(15.24,0) 14(16.51,-1.905) 15(17.78,0) 16(19.05,-1.905) 17(20.32,0) 18(21.59,-1.905) 19(22.86,0) 20(24.13,-1.905) 21(25.4,0) 22(26.67,-1.905) 23(27.94,0) 24(29.21,-1.905) 25(30.48,0) 26(31.75,-1.905) 27(33.02,0) 28(34.29,-1.905) 29(35.56,0) 30(36.83,-1.905) 31(38.1,0) 32(39.37,-1.905) 33(40.64,0) 34(41.91,-1.905) 35(43.18,0) 36(44.45,-1.905) 37(45.72,0) 38(46.99,-1.905) 39(48.26,0) 40(49.53,-1.905) 41(50.8,0) 42(52.07,-1.905) 43(53.34,0) 44(54.61,-1.905) 45(55.88,0) 46(57.15,-1.905) 47(58.42,0) 48(59.69,-1.905) 49(60.96,0) 50(62.23,-1.905) 51(0,3.81) 52(1.27,1.905) 53(2.54,3.81) 54(3.81,1.905) 55(5.08,3.81) 56(6.35,1.905) 57(7.62,3.81) 58(8.89,1.905) 59(10.16,3.81) 60(11.43,1.905) 61(12.7,3.81) 62(13.97,1.905) 63(15.24,3.81) 64(16.51,1.905) 65(17.78,3.81) 66(19.05,1.905) 67(20.32,3.81) 68(21.59,1.905) 69(22.86,3.81) 70(24.13,1.905) 71(25.4,3.81) 72(26.67,1.905) 73(27.94,3.81) 74(29.21,1.905) 75(30.48,3.81) 76(31.75,1.905) 77(33.02,3.81) 78(34.29,1.905) 79(35.56,3.81) 80(36.83,1.905) 81(38.1,3.81) 82(39.37,1.905) 83(40.64,3.81) 84(41.91,1.905) 85(43.18,3.81) 86(44.45,1.905) 87(45.72,3.81) 88(46.99,1.905) 89(48.26,3.81) 90(49.53,1.905) 91(50.8,3.81) 92(52.07,1.905) 93(53.34,3.81) 94(54.61,1.905) 95(55.88,3.81) 96(57.15,1.905) 97(58.42,3.81) 98(59.69,1.905) 99(60.96,3.81) 100(62.23,1.905)
  round 2.5 hole 2.77: 101(-8.01,1.905) 102(70.24,1.905)
  silkscreen extent -10.97,-2.67 73.2,7.87
SO3 [mm]
  rect 0.9x1.27 smd: 1(2.972,-3.601)
  rect 0.9x0.95 smd: 2(2.022,-6.101) 3(3.922,-6.101)
  silkscreen extent 0.9,-6.23 4.27,-3.6
SOIC8_L [mm] "SOIC, 8-Leads, Body 4.9x3.9mm, Pitch 1.27mm, IPC High Density"
  oval 1.9x0.6 smd: 1(-2.35,1.905) 2(-2.35,0.635) 3(-2.35,-0.635) 4(-2.35,-1.905) 5(2.35,-1.905) 6(2.35,-0.635) 7(2.35,0.635) 8(2.35,1.905)
  silkscreen extent -2.47,-2.5 1,2.88, body extent -1.95,-2.45 1.95,2.45, height 1.75
SOP20 [mil]
  rect 100x22 smd: 1(0,0)
  oval 100x22 smd: 2(0,-50) 3(0,-100) 4(0,-150) 5(0,-200) 6(0,-250) 7(0,-300) 8(0,-350) 9(0,-400) 10(0,-450) 11(350,-450) 12(350,-400) 13(350,-350) 14(350,-300) 15(350,-250) 16(350,-200) 17(350,-150) 18(350,-100) 19(350,-50) 20(350,0)
  silkscreen extent 85,-475 265,25
SSOP48 [mm]
  rect 2x0.28 smd: 1(0,0)
  oval 2x0.28 smd: 2(0,-0.5) 3(0,-1) 4(0,-1.5) 5(0,-2) 6(0,-2.5) 7(0,-3) 8(0,-3.5) 9(0,-4) 10(0,-4.5) 11(0,-5) 12(0,-5.5) 13(0,-6) 14(0,-6.5) 15(0,-7) 16(0,-7.5) 17(0,-8) 18(0,-8.5) 19(0,-9) 20(0,-9.5) 21(0,-10) 22(0,-10.5) 23(0,-11) 24(0,-11.5) 25(8,-11.5) 26(8,-11) 27(8,-10.5) 28(8,-10) 29(8,-9.5) 30(8,-9) 31(8,-8.5) 32(8,-8) 33(8,-7.5) 34(8,-7) 35(8,-6.5) 36(8,-6) 37(8,-5.5) 38(8,-5) 39(8,-4.5) 40(8,-4) 41(8,-3.5) 42(8,-3) 43(8,-2.5) 44(8,-2) 45(8,-1.5) 46(8,-1) 47(8,-0.5) 48(8,0)
  silkscreen extent 1.84,-11.75 6.16,0.25
TLP281-4 [mm]
  rect 2x0.5 smd: 1(0,0)
  oval 2x0.5 smd: 2(0,-1.27) 3(0,-2.54) 4(0,-3.81) 5(0,-5.08) 6(0,-6.35) 7(0,-7.62) 8(0,-8.89) 9(7,-8.89) 10(7,-7.62) 11(7,-6.35) 12(7,-5.08) 13(7,-3.81) 14(7,-2.54) 15(7,-1.27) 16(7,0)
  silkscreen extent 1.84,-9.53 5.17,0.64

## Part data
C1 C3 C7 C111 C113 C115 C117: "Polarized Capacitor (Surface Mount)"
C2 C5 C6 C9 C10 C11 C12 C13 C14 C15 C16 C17 C18 C19 C20 C21 C22 C31 C32 C33 C34 C35 C36 C37 C38 C39 C40 C41 C42 C61 C62 C63 C64 C65 C66 C67 C68 C71 C72 C73 C74 C75 C76 C77 C78 C81 C82 C83 C84 C85 C86 C87 C88 C112 C114 C116 C118 C121: "Capacitor (Semiconductor SIM Model)"
D1 D2 D3 D4 D5 D6 D7 D8 D11 D12 D13 D14 D15 D16 D17 D18 D19: "Default Diode"
J1: "Receptacle Header Assemby"
J2 J3: "Header, 5-Pin, Dual row"
J4: "Z-Pack 2mm Hard Metric Type A 110 Position Female PCB Mount Connector"
J5: "Z-Pack 2mm Hard Metric Type B 110 Position Female Daughter Card Connector"
J7 J8: library part "Header 5X2", "Header, 5-Pin, Dual row"
LED1 LED2 LED3 LED4 LED5 LED6 LED7 LED8 LED9: "Typical RED, GREEN, YELLOW, AMBER GaAs LED"
Q1 Q2 Q3 Q4 Q5 Q6 Q7 Q8: "NPN Bipolar Transistor"
R1 R2 R3 R4 R5 R6 R7 R8 R9 R10 R11 R12 R13 R14 R15 R16 R17 R18 R19 R20 R21 R22 R23 R24 R25 R26 R27 R28 R29 R30 R31 R32 R33 R34 R35 R36 R37 R38 R39 R40 R41 R42 R45 R48 R51 R54 R55 R56 R57 R58 R61 R64 R67 R70 R71 R72 R73 R74 R81 R82 R83 R84 R85 R86 R87 R88 R91 R92 R93 R94 R95 R96 R97 R98 R100 R101 R102 R103 R104 R105 R106 R107 R108 R109 R110 R111 R112 R113 R114 R115 R116 R120 R121 R122 R123 R124 R125 R126 R127 R130 R131 R132 R133 R134 R135 R136 R137 R138 R139 R200: "Semiconductor Resistor"
R75 R76 R77 R78 R79 R80: "Resistor Array - Parts"
U1: "Cyclone Family, 1.5V FPGA, 173 I/O Pins, 2 x PLLs, Commercial Grade, Speed Grade 6"
U2: "EPCS1 Series, In-system programmable 3.3V serial configuration device, 8-Pin SOIC, 1-Megabit, Industrial Grade"
VR1 VR2: library part "Volt Reg", "Voltage Regulator"
X1: library part OSCIL

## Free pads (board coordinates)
  round 94.49 hole 106.3 unplated: MH1(0,0) MH2(0,3500) MH3(5374.02,0) MH4(5374.02,3500)
  round 66.93 hole 78.74 unplated: MH5(5784.65,883.86) MH6(6020.87,883.86)

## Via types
v1: diameter 24, hole 12, Top Layer to Bottom Layer, 232 vias
v2: diameter 36, hole 18, Top Layer to Bottom Layer, 6 vias
v3: diameter 24, hole 12, Top Layer to Bottom Layer, tented bottom, 1 vias

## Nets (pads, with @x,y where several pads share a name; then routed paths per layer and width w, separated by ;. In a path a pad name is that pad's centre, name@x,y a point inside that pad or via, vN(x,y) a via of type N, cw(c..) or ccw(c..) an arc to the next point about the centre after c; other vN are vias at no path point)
1.5V: C11.2 C12.2 C13.2 C14.2 C15.2 C16.2 C17.2 C18.2 C19.2 C20.2 C21.2 C22.2 C117.1 C118.2 L1.1 L2.1 U1.72 U1.81 U1.90 U1.97 U1.103 U1.110 U1.191 U1.198 U1.204 U1.211 U1.220 U1.229 VR2.2 | length 8405.1
  Top Layer w10: v1(3976.38,1732.28) 3996.06,1732.28 ; v1(4045.28,767.72) 4084.65,728.35 4084.65,639.76 4104.33,620.08 ; U1.97@4242.13,568.9 4242.13,620.08 4271.65,649.61 4271.65,728.35 v1(4311.02,767.72) ; VR2.2@4634.04,3086.61 VR2.2@4634.04,3102.18
  Top Layer w12: U1.72@3750,568.9 3750,610.24 3769.69,629.92 3769.69,659.45 v1(3877.95,767.72) ; U1.229@3750,1931.1 3750,1781.5 v1(3799.21,1732.28) ; U1.81@3927.17,568.9 3927.17,620.08 4104.33,620.08 U1.90@4104.33,568.9 ; U1.220@3927.17,1931.1 3927.17,1781.5 v1(3976.38,1732.28) 4045.28,1732.28 4104.33,1791.34 U1.211@4104.33,1931.1 ; U1.204@4242.13,1931.1 4242.13,1771.65 v1(4281.5,1732.28) 4360.24,1811.02 U1.198@4360.24,1931.1 ; U1.103@4360.24,568.9 4360.24,620.08 4498.03,620.08 ; v1(4438.98,1732.28) 4498.03,1791.34 U1.191@4498.03,1931.1 ; v1(4468.5,767.72) 4498.03,738.19 4498.03,620.08 ; U1.110@4498.03,568.9 4498.03,620.08
  Top Layer w40: v1(3927.17,1181.1) 3927.17,816.93 v1(3877.95,767.72) v1(4045.28,767.72) ; v1(4301.18,1181.1) 4301.18,935.04 v1(4468.5,767.72) v1(4311.02,767.72) ; v1(4498.03,2224.41) 4498.03,2844.49 4634.04,2980.5 VR2.2@4634.04,3086.61 ; v2(4586.61,3149.61) VR2.2@4634.04,3102.18
  Bottom Layer w10: C20.2@4311.02,722.44 v1(4311.02,767.72) ; v2(4586.61,3149.61) v2@4586.61,3153.54 ; C117.1@4639.76,3208.66 C117.1@4641.73,3208.66
  Bottom Layer w12: 3799.21,1692.91 v1(3799.21,1732.28) C11.2@3799.21,1777.56 C12.2@3858.27,1777.56 ; C17.2@3877.95,722.44 v1(3877.95,767.72) ; v1(3927.17,1181.1) L1.1@3927.17,1246.06 ; 3976.38,1692.91 3976.38,1702.76 v1(3976.38,1732.28) C13.2@3976.38,1777.56 ; C19.2@3986.22,722.44 C18.2@4045.28,722.44 v1(4045.28,767.72) ; 4281.5,1692.91 v1(4281.5,1732.28) C14.2@4281.5,1777.56 C15.2@4340.55,1777.56 ; v1(4301.18,1181.1) L2.1@4301.18,1246.06 ; C21.2@4409.45,722.44 C22.2@4468.5,722.44 v1(4468.5,767.72) ; 4438.98,1692.91 v1(4438.98,1732.28) C16.2@4438.98,1777.56
  Bottom Layer w40: 3799.21,1692.91 3966.54,1692.91 ; v1(3927.17,1181.1) 3986.22,1240.16 3986.22,1673.23 3966.54,1692.91 ; 3976.38,1702.76 3976.38,1692.91 ; v1(4301.18,1181.1) 4251.97,1230.31 4251.97,1692.91 ; v1(4498.03,2224.41) 4498.03,1692.91 4251.97,1692.91 ; C118.2@4551.18,3297.24 C117.1@4639.76,3208.66 ; v2@4586.61,3153.54 C117.1@4641.73,3208.66 ; 3966.54,1692.91 3976.38,1692.91 ; 3976.38,1692.91 4251.97,1692.91
3.3V: C1.1 C2.2 C31.2 C32.2 C33.2 C34.2 C35.2 C36.2 C37.2 C38.2 C39.2 C40.2 C41.2 C42.2 C113.1 C114.2 J2.4 J3.4 R1.2 R2.2 R5.1 R6.1 R7.1 R8.1 R130.2 R131.2 R132.2 R133.2 R134.2 U1.9 U1.22 U1.51 U1.70 U1.92 U1.112 U1.130 U1.157 U1.172 U1.189 U1.209 U1.231 U2.3 U2.7 U2.8 U3.10 U3.12 U3.14 U3.16 U4.10 U4.12 U4.14 U4.16 U5.10 U5.12 U5.14 U5.16 U6.10 U6.12 U6.14 U6.16 U7.10 U7.12 U7.14 U7.16 U8.10 U8.12 U8.14 U8.16 VR1.2 X1.4 | length 23854.6
  Top Layer w10: U6.10@984.25,1555.12 v1(1112.2,1555.12) ; U6.16@984.25,1850.39 v1(1112.2,1850.39) ; U6.12@994.09,1653.54 v1(1112.2,1653.54) ; U8.10@1003.94,265.75 v1(1112.2,265.75) ; U4.10@1003.94,915.35 v1(1112.2,915.35) ; U4.14@1003.94,1112.2 v1(1112.2,1112.2) ; U8.12@1013.78,364.17 v1(1112.2,364.17) ; U8.14@1013.78,462.6 v1(1112.2,462.6) ; U8.16@1013.78,561.02 v1(1112.2,561.02) ; U4.12@1013.78,1013.78 v1(1112.2,1013.78) ; U4.16@1013.78,1210.63 v1(1112.2,1210.63) ; U6.14@1013.78,1751.97 v1(1112.2,1751.97) ; U3.10@1692.91,915.35 v1(1820.87,915.35) ; U3.12@1692.91,1013.78 v1(1820.87,1013.78) ; U3.14@1692.91,1112.2 v1(1820.87,1112.2) ; U7.10@1702.76,275.59 v1(1820.87,275.59) ; U7.14@1702.76,472.44 v1(1820.87,472.44) ; U5.10@1702.76,1545.28 v1(1820.87,1545.28) ; U5.12@1702.76,1643.7 v1(1820.87,1643.7) ; U5.14@1702.76,1742.13 v1(1820.87,1742.13) ; U5.16@1702.76,1840.55 v1(1820.87,1840.55) ; U7.12@1712.6,374.02 v1(1820.87,374.02) ; U7.16@1712.6,570.87 v1(1820.87,570.87) ; U3.16@1712.6,1210.63 v1(1820.87,1210.63) ; U2.3@2515.75,939.57 2543.9,939.57 2593.9,989.57 U2.7@2671.26,989.57 ; U2.8@2671.26,1029.53 U2.7@2671.26,989.57 ; J3.4@2951.18,1103.94 2895.28,1103.94 2780.91,989.57 U2.7@2671.26,989.57 ; v1(3257.87,216.54) 3257.87,374.02 3661.42,777.56 v1(3661.42,807.09) 3622.05,846.46 U1.51@3433.07,846.46 ; U1.92@4143.7,568.9 4143.7,718.5 v1(4192.91,767.72) 4192.91,1181.1 4242.13,1230.31 4370.08,1230.31 ; VR1.2@5452.76,3100.39 VR1.2@5452.76,3110.24
  Top Layer w12: J2.4@2951.18,247.64 3001.97,196.85 3238.19,196.85 v1(3257.87,216.54) ; v1(3139.76,374.02) 3257.87,374.02 ; U1.22@3433.07,1417.32 3582.68,1417.32 v1(3631.89,1466.54) ; U1.9@3433.07,1673.23 3562.99,1673.23 v1(3631.89,1604.33) ; v1(3533.46,1801.18) 3661.42,1801.18 3710.63,1850.39 U1.231@3710.63,1931.1 ; v1(3661.42,807.09) 3710.63,757.87 U1.70@3710.63,568.9 ; U1.209@4143.7,1931.1 4143.7,1761.81 v1(4173.23,1732.28) 4173.23,1663.39 ; v1(4409.45,88.58) 4449.71,88.58 X1.4@4514.98,23.31 ; 4534.62,853.51 v1(4596.46,915.35) 4655.51,856.3 4744.09,856.3 4753.94,846.46 U1.130@4795.28,846.46 ; U1.112@4537.4,568.9 4537.4,610.24 4566.93,639.76 4566.93,718.5 v1(4616.14,767.72) ; U1.189@4537.4,1931.1 4537.4,1889.76 4625.98,1801.18 v1(4625.98,1732.28) ; v1(4596.46,1456.69) 4675.2,1377.95 U1.157@4795.28,1377.95 ; v1(4596.46,1594.49) 4675.2,1673.23 U1.172@4795.28,1673.23
  Top Layer w40: v1(3533.46,1801.18) 3690.94,1643.7 ; v1(3661.42,807.09) v1(3661.42,1072.83) 3661.42,1437.01 v1(3631.89,1466.54) v1(3631.89,1604.33) 3690.94,1643.7 ; 4557.09,1633.86 v1(4596.46,1594.49) v1(4596.46,1456.69) 4370.08,1230.31 4370.08,1013.78 v1(4616.14,767.72) ; v1(4625.98,1732.28) 4557.09,1643.7 3690.94,1643.7 ; v1(4990.16,2224.41) 4990.16,2312.99 5460.81,2783.65 VR1.2@5460.81,3076.77 ; v2(5423.23,3139.76) VR1.2@5452.76,3110.24
  Bottom Layer w10: J3.4@2951.18,1103.94 2998.82,1151.57 3188.98,1151.57 ; R1.2@3212.6,216.54 v1(3257.87,216.54) ; R8.1@3212.6,1007.87 R5.1@3212.6,1072.83 ; R7.1@3212.6,1200.79 3212.6,1175.2 3188.98,1151.57 ; R6.1@3214.57,944.88 R8.1@3214.57,1000 ; v1(3533.46,1801.18) 3557.09,1777.56 C31.2@3622.05,1777.56 ; C39.2@3661.42,718.5 C39.2@3661.42,722.44 ; v1(3661.42,1072.83) R5.1@3212.6,1072.83 ; C113.1@5452.76,3169.29 C113.1@5452.76,3179.13 ; C113.1@5466.54,3198.82 C113.1@5468.5,3198.82 ; 3188.98,1151.57 3212.6,1127.95 R5.1@3212.6,1072.83
  Bottom Layer w12: R130.2@2401.57,531.5 2401.57,88.58 2431.1,59.06 2834.65,59.06 2883.86,108.27 2883.86,180.32 J2.4@2951.18,247.64 ; v1(3139.76,374.02) R2.2@3139.76,423.23 ; C41.2@3586.61,1466.54 v1(3631.89,1466.54) ; C42.2@3586.61,1604.33 v1(3631.89,1604.33) ; C40.2@3592.52,807.09 v1(3661.42,807.09) C39.2@3661.42,722.44 ; v1(4173.23,1732.28) C32.2@4173.23,1777.56 ; v1(4192.91,767.72) 4143.7,718.5 4143.7,153.54 C2.2@4212.6,84.65 4405.51,84.65 v1(4409.45,88.58) C1.1@4409.45,265.75 ; v1(4596.46,915.35) C36.2@4641.73,915.35 ; v1(4596.46,1456.69) C35.2@4641.73,1456.69 ; v1(4596.46,1594.49) C34.2@4641.73,1594.49 ; C37.2@4616.14,722.44 v1(4616.14,767.72) ; v1(4625.98,1732.28) C33.2@4625.98,1777.56
  Bottom Layer w40: v1(1112.2,265.75) v1(1112.2,364.17) v1(1112.2,462.6) v1(1112.2,561.02) 1210.63,659.45 1692.91,659.45 1820.87,787.4 ; v1(1112.2,915.35) v1(1112.2,1013.78) v1(1112.2,1112.2) v1(1112.2,1210.63) 1200.79,1299.21 1702.76,1299.21 1820.87,1417.32 ; v1(1112.2,1555.12) v1(1112.2,1653.54) v1(1112.2,1751.97) v1(1112.2,1850.39) 1210.63,1948.82 1919.29,1948.82 ; v1(1820.87,275.59) v1(1820.87,374.02) v1(1820.87,472.44) v1(1820.87,570.87) 1820.87,787.4 ; v1(1820.87,1840.55) v1(1820.87,1742.13) v1(1820.87,1643.7) v1(1820.87,1545.28) 1820.87,1417.32 ; v1@1820.87,1850.39 1919.29,1948.82 ; v1(3533.46,1801.18) 3385.83,1948.82 1919.29,1948.82 ; 4648.62,1754.92 4990.16,2096.46 v1(4990.16,2224.41) ; C114.2@5377.95,3287.4 C113.1@5466.54,3198.82 ; v2(5423.23,3139.76) C113.1@5452.76,3169.29 ; 1820.87,787.4 v1(1820.87,915.35) v1(1820.87,1013.78) v1(1820.87,1112.2) v1(1820.87,1210.63) 1820.87,1417.32
5V: C111.1 C112.2 C115.1 C116.2 D1.2 D2.2 D3.2 D4.2 D5.2 D6.2 D7.2 D8.2 D11.2 D12.2 D13.2 D14.2 D15.2 D16.2 D17.2 D18.2 D19.1 J1.25 J1.26 J1.75 J1.76 J4.A1 J4.A25 J4.B2 J4.B24 J4.D3 J4.D23 J4.E1 J4.E25 J6.1 LED9.1 R81.2 R82.2 R83.2 R84.2 R85.2 R86.2 R87.2 R88.2 R91.2 R92.2 R93.2 R94.2 R95.2 R96.2 R97.2 R98.2 U9.9 U10.9 U11.9 U12.9 U13.9 U14.9 U15.9 U16.9 U17.9 U18.9 U19.9 U20.9 U21.9 U22.9 U23.9 U24.9 U25.20 U26.20 VR1.3 VR2.3 | length 25399.3
  Top Layer w10: U26.20@3380.31,2234.25 v1(3474.41,2234.25) ; U25.20@3380.31,2883.86 v1(3494.09,2883.86) ; LED9.1@4625.98,3507.87 LED9.1@4625.98,3513.78
  Top Layer w12: LED9.1@4625.98,3507.87 v1@4681.1,3507.87
  Top Layer w40: VR2.3@4724.04,3086.61 4793.31,3017.35 ; v2(4793.31,2992.13) 4842.52,3041.34 J6.1@5131.58,3041.34 ; J6.1@5131.58,3040.77 5289.63,3198.82 5491.39,3198.82 5550.81,3139.39 VR1.3@5550.81,3076.77 5620.08,3007.5 v2(5620.08,2982.28)
  Bottom Layer w10: 3586.61,2736.22 3586.61,2966.54 ; D19.1@5192.91,1529.53 D19.1@5192.91,1525.59 5192.91,1610.24 ; v2@5610.24,2982.28 v2(5620.08,2982.28)
  Bottom Layer w12: 620.08,2535.43 622.44,2537.8 U24.9@714.96,2537.8 ; 639.76,3188.98 641.34,3187.4 U16.9@714.96,3187.4 ; D8.2@679.13,3041.34 722.44,2998.03 R88.2@722.44,2962.6 ; D8.2@708.66,3100.39 714.96,3106.69 U16.9@714.96,3187.4 ; D18.2@718.5,2421.26 722.44,2417.32 R98.2@722.44,2322.83 ; D18.2@718.5,2431.1 714.96,2434.65 U24.9@714.96,2537.8 ; 836.61,2716.54 767.72,2647.64 767.72,2590.55 U24.9@714.96,2537.8 ; 836.61,3503.94 767.72,3435.04 767.72,3240.16 U16.9@714.96,3187.4 ; 964.57,3185.04 966.93,3187.4 U15.9@1059.45,3187.4 ; 974.41,2539.37 975.98,2537.8 U23.9@1059.45,2537.8 ; D17.2@1062.99,2411.42 1066.93,2407.48 R97.2@1066.93,2322.83 ; D17.2@1062.99,2440.94 1059.45,2444.49 U23.9@1059.45,2537.8 ; D7.2@1062.99,3061.02 1066.93,3057.09 R87.2@1066.93,2962.6 ; D7.2@1062.99,3080.71 1059.45,3084.25 U15.9@1059.45,3187.4 ; 1166.34,2711.61 1112.2,2657.48 1112.2,2590.55 U23.9@1059.45,2537.8 ; 1190.94,3503.94 1112.2,3425.2 1112.2,3240.16 U15.9@1059.45,3187.4 ; 1309.06,3185.04 1401.57,3185.04 U14.9@1403.94,3187.4 ; 1318.9,2539.37 1320.47,2537.8 U22.9@1403.94,2537.8 ; D16.2@1368.11,2401.57 1411.42,2358.27 R96.2@1411.42,2322.83 ; D6.2@1368.11,3041.34 1411.42,2998.03 R86.2@1411.42,2962.6 ; D16.2@1397.64,2450.79 1403.94,2457.09 U22.9@1403.94,2537.8 ; D6.2@1407.48,3090.55 1403.94,3094.09 U14.9@1403.94,3187.4 ; 1515.75,2716.54 1456.69,2657.48 1456.69,2590.55 U22.9@1403.94,2537.8 ; 1525.59,3503.94 1456.69,3435.04 1456.69,3240.16 U14.9@1403.94,3187.4 ; 1653.54,3198.82 1664.96,3187.4 U13.9@1748.43,3187.4 ; 1673.23,2539.37 1674.8,2537.8 U21.9@1758.27,2537.8 ; D15.2@1732.28,2401.57 1765.75,2368.11 R95.2@1765.75,2322.83 ; D5.2@1742.13,3100.39 1748.43,3106.69 U13.9@1748.43,3187.4 ; R85.2@1755.91,2962.6 1755.91,3055.12 D5.2@1761.81,3061.02 ; D15.2@1758.27,2444.49 U21.9@1758.27,2537.8 ; 1870.08,2716.54 1811.02,2657.48 1811.02,2590.55 U21.9@1758.27,2537.8 ; 1870.08,3503.94 1801.18,3435.04 1801.18,3240.16 U13.9@1748.43,3187.4 ; 1998.03,2539.37 1999.61,2537.8 U20.9@2092.91,2537.8 ; 1998.03,3185.04 2000.39,3187.4 U12.9@2092.91,3187.4 ; D14.2@2092.91,2437.4 U20.9@2092.91,2537.8 ; D4.2@2096.46,3100.39 2092.91,3103.94 U12.9@2092.91,3187.4 ; R94.2@2100.39,2312.99 2100.39,2405.51 D14.2@2106.3,2411.42 ; R84.2@2100.39,2962.6 2100.39,3045.28 D4.2@2106.3,3051.18 ; 2194.88,2716.54 2145.67,2667.32 2145.67,2590.55 U20.9@2092.91,2537.8 ; 2214.57,3503.94 2145.67,3435.04 2145.67,3240.16 U12.9@2092.91,3187.4 ; 2344.88,3187.4 U11.9@2437.4,3187.4 ; 2352.36,2535.43 2354.72,2537.8 U19.9@2437.4,2537.8 ; D3.2@2411.42,3041.34 2444.88,3007.87 R83.2@2444.88,2962.6 ; D3.2@2431.1,3080.71 2437.4,3087.01 U11.9@2437.4,3187.4 ; D13.2@2440.94,2411.42 2444.88,2407.48 R93.2@2444.88,2312.99 ; D13.2@2440.94,2431.1 2437.4,2434.65 U19.9@2437.4,2537.8 ; 2549.21,2716.54 2490.16,2657.48 2490.16,2590.55 U19.9@2437.4,2537.8 ; 2559.06,3503.94 2490.16,3435.04 2490.16,3240.16 U11.9@2437.4,3187.4 ; 2687.01,2545.28 2694.49,2537.8 U18.9@2781.89,2537.8 ; 2706.69,3185.04 2709.06,3187.4 U10.9@2791.73,3187.4 ; R92.2@2789.37,2312.99 2789.37,2407.48 2781.89,2414.96 U18.9@2781.89,2537.8 ; D2.2@2795.28,3100.39 2791.73,3103.94 U10.9@2791.73,3187.4 ; R82.2@2799.21,2962.6 2799.21,3035.43 D2.2@2805.12,3041.34 ; 2893.7,2716.54 2834.65,2657.48 2834.65,2590.55 U18.9@2781.89,2537.8 ; 2913.39,3503.94 2844.49,3435.04 2844.49,3240.16 U10.9@2791.73,3187.4 ; 3031.5,2535.43 3033.86,2537.8 U17.9@3126.38,2537.8 ; 3041.34,3185.04 3133.86,3185.04 U9.9@3136.22,3187.4 ; D11.2@3129.92,2421.26 3133.86,2417.32 R91.2@3133.86,2312.99 ; D11.2@3129.92,2440.94 3126.38,2444.49 U17.9@3126.38,2537.8 ; D1.2@3139.76,3041.34 3143.7,3037.4 R81.2@3143.7,2962.6 ; D1.2@3139.76,3090.55 3136.22,3094.09 U9.9@3136.22,3187.4 ; 3248.03,2716.54 3179.13,2647.64 3179.13,2590.55 U17.9@3126.38,2537.8 ; 3257.87,3503.94 3188.98,3435.04 3188.98,3240.16 U9.9@3136.22,3187.4 ; 3586.61,3375.98 3586.61,3440.94 3641.73,3496.06 3641.73,3503.94 ; 5236.22,1978.35 5344.49,1870.08 5743.31,1870.08 ; 5531.5,-19.68 5743.31,-19.68 ; J4.E1@5784.65,-61.02 5743.31,-19.68 ; J4.E25@5784.65,1828.74 5743.31,1870.08 ; J4.D3@5863.39,96.46 5905.51,54.33 5905.51,0 5925.2,-19.68 ; J4.D23@5863.39,1671.26 5904.72,1712.6 5983.46,1712.6 J4.B24@6020.87,1750 J4.A25@6099.61,1828.74 6058.27,1870.08 5743.31,1870.08 ; J4.B2@6020.87,17.72 6058.27,-19.68 ; J4.A1@6099.61,-61.02 6058.27,-19.68 ; 5743.31,-19.68 5925.2,-19.68 ; 5925.2,-19.68 6058.27,-19.68
  Bottom Layer w40: 836.61,2716.54 1515.75,2716.54 1870.08,2716.54 2194.88,2716.54 2549.21,2716.54 2893.7,2716.54 3248.03,2716.54 3326.77,2716.54 3848.43,3238.19 3848.43,3444.88 3849.4,3443.91 3909.43,3503.94 v1(4685.04,3503.94) 4734.25,3503.94 4793.31,3444.88 v2(4793.31,2992.13) C116.2@4738.19,2992.13 4738.19,3033.46 C115.1@4690.94,3080.71 ; 836.61,3503.94 1190.94,3503.94 1525.59,3503.94 1870.08,3503.94 2214.57,3503.94 2559.06,3503.94 2913.39,3503.94 3257.87,3503.94 3641.73,3503.94 3907.48,3503.94 ; C111.1@5517.72,3070.87 5564.96,3023.62 C112.2@5564.96,2982.28 v2(5620.08,2982.28) 5620.08,2824.8 5236.22,2440.94 5236.22,1978.35 5236.22,1673.23 4921.26,1358.27 4921.26,206.69 5029.53,98.43 5413.39,98.43 5531.5,-19.68
ASDO: J3.9 U1.37 U2.5 | length 1526.6
  Top Layer w10: U2.5@2706.89,885.83 v3(2736.22,885.83) 3021.65,885.83 3257.87,1122.05 U1.37@3433.07,1122.05
  Bottom Layer w10: v3(2736.22,885.83) 2736.22,1181.1 2913.39,1358.27 3005.51,1358.27 J3.9@3051.18,1403.94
